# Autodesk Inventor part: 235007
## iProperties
Created: 2006-08
Part Number: 235007
Material: 8 vz
Description: Sechskantmutter
Vendor: Autodesk Inc.
Document SubType Name: Modeling
Standard: DIN 934
Designer: I.Baliuc
Standards Organization: DIN
Language: de-DE
Size Designation: M6
Categories: <MemberInstance Version="R10.0.0"><Categories><Category DisplayName="Schrauben" InternalName="e4da775c-781d-43d5-af7c-5136215cf5a6" Mnemonic="FSTN"><Category Di
Density: 7.85 g/cm^3
Mass: 2.52173 g
Surface Area: 3.5226 cm^2
Volume: 0.321239 cm^3
Abmessung: M6
Author: T.Messerschmitt
Comments: DIN 934 - M6
Revision Number: 235007
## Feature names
1. Körper [Extrusion]
2. Fase1 [Revolution]
3. Gewinde [Hole]
4. Fase2 [Chamfer]
5. Fase3 [Chamfer]
